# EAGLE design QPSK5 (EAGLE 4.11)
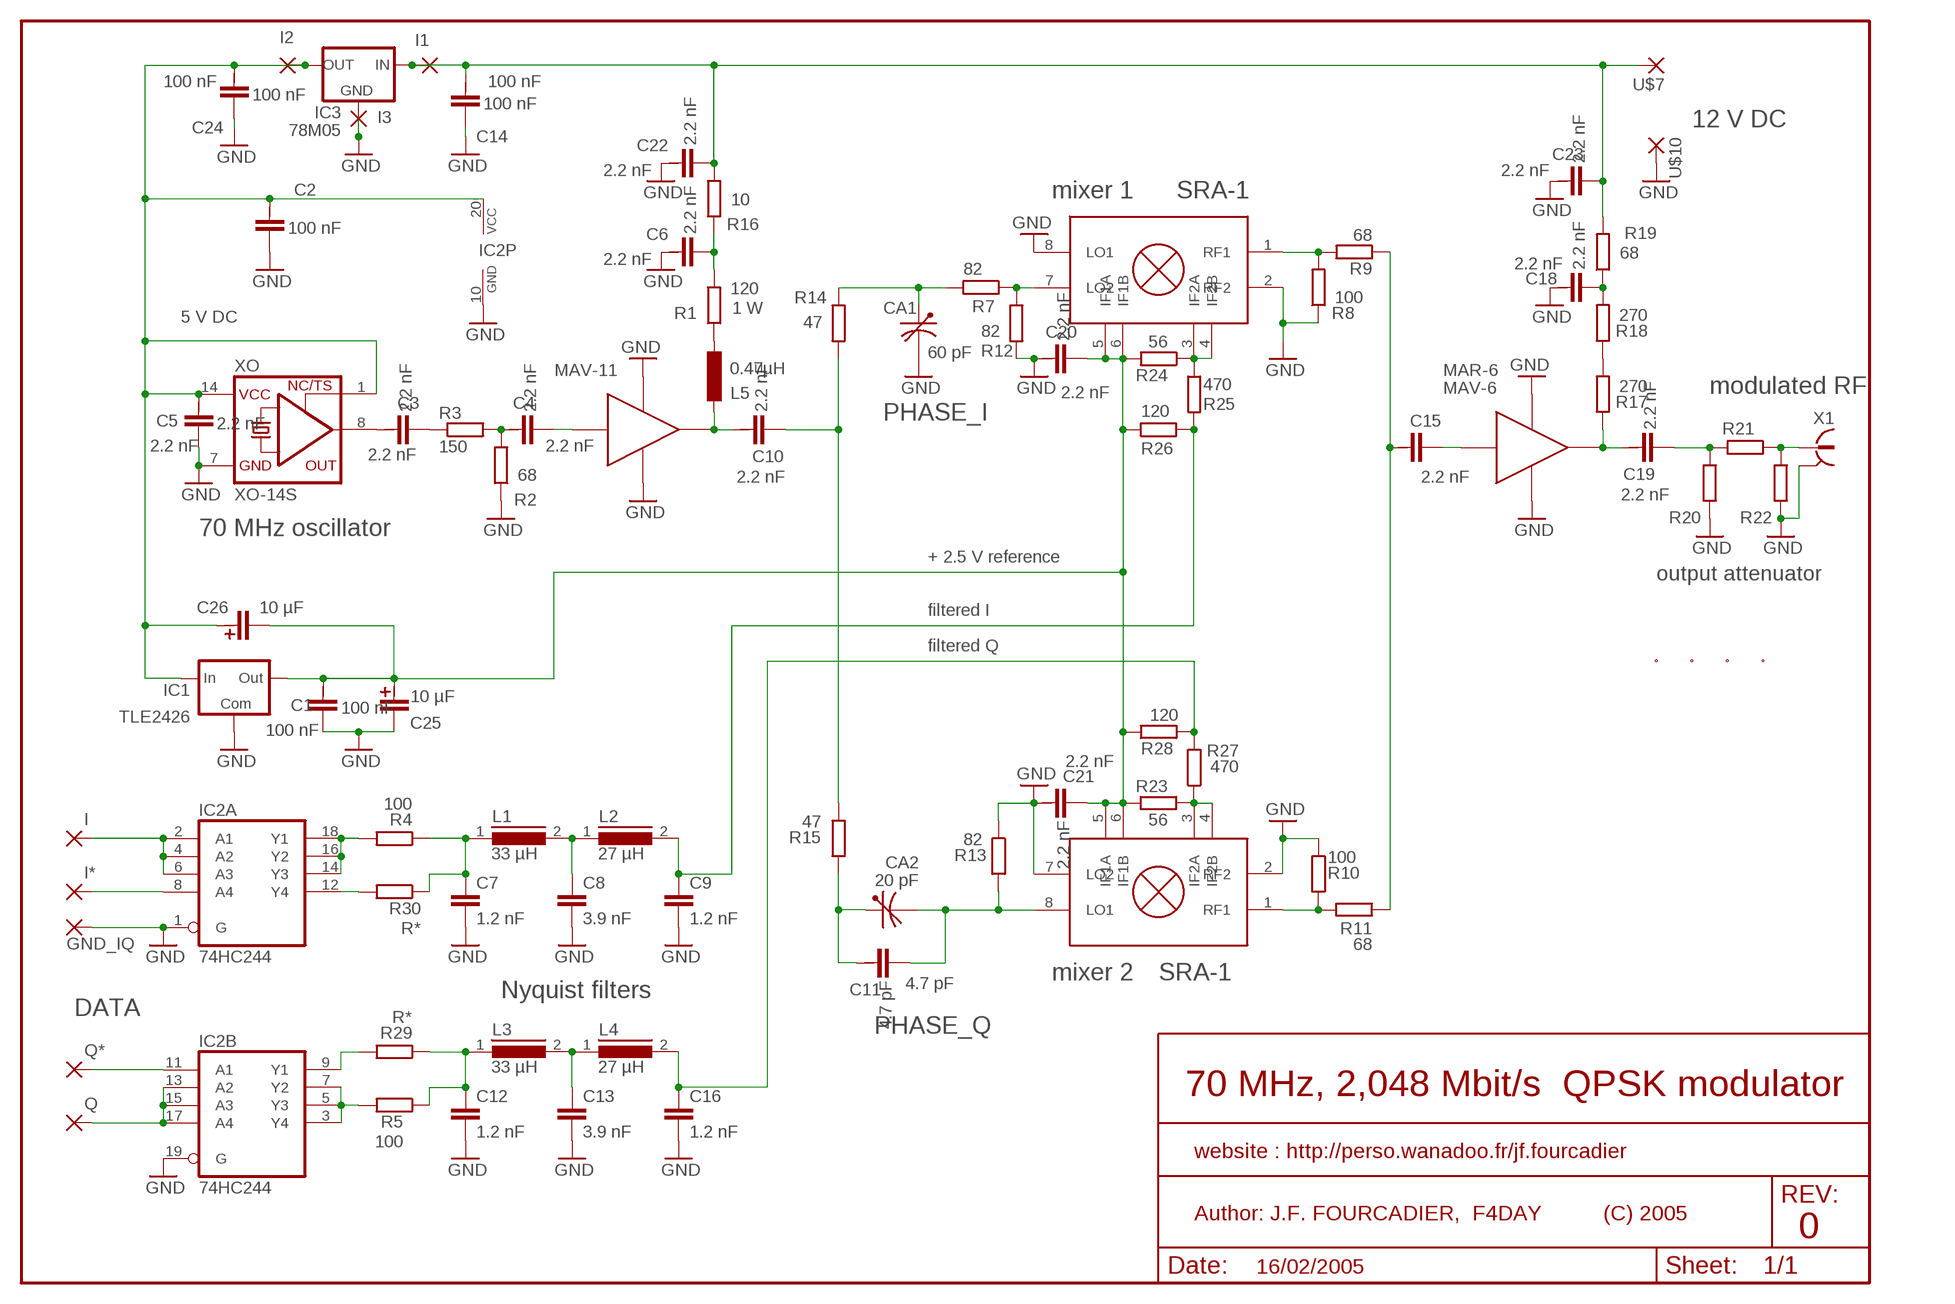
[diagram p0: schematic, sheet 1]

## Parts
C1  100 nF  C1206  [C1206]
C2  100 nF  C1206  [C1206]
C3  2.2 nF  C1206  [C1206]
C4  2.2 nF  C1206  [C1206]
C5  2.2 nF  C1206  [C1206]
C6  2.2 nF  C1206  [C1206]
C7  1.2 nF  C-EU050-035X075  [C050-035X075]
C8  3.9 nF  C-EU050-035X075  [C050-035X075]
C9  1.2 nF  C-EU050-035X075  [C050-035X075]
C10  2.2 nF  C1206  [C1206]
C11  4.7 pF  C1206  [C1206]
C12  1.2 nF  C-EU050-035X075  [C050-035X075]
C13  3.9 nF  C-EU050-035X075  [C050-035X075]
C14  100 nF  C1206  [C1206]
C15  C1206  [C1206]
C16  1.2 nF  C-EU050-035X075  [C050-035X075]
C18  2.2 nF  C1206  [C1206]
C19  2.2 nF  C1206  [C1206]
C20  2.2 nF  C1206  [C1206]
C21  2.2 nF  C1206  [C1206]
C22  2.2 nF  C1206  [C1206]
C23  2.2 nF  C1206  [C1206]
C24  100 nF  C1206  [C1206]
C25  10 µF  CT6032  [CT6032]
C26  10 µF  CT6032  [CT6032]
CA1  60 pF  MURATA  [MURATA_F]
CA2  20 pF  MURATA  [MURATA_F]
GND_IQ  2,54/0,4  [2,54/0,4]
I  2,54/0,4  [2,54/0,4]
I1  2,54/0,4  [2,54/0,4]
I2  2,54/0,4  [2,54/0,4]
I3  2,54/0,4  [2,54/0,4]
I*  2,54/0,4  [2,54/0,4]
IC1  TLE2426  TLE2425  [TLE2425]
IC2  74HC244  74HC244DW  [SO20W]
IC3  78M05  78XXL  [78XXL]
L1  33 µH  MMICC7  [MMICC7]
L2  27 µH  MMICC7  [MMICC7]
L3  33 µH  MMICC7  [MMICC7]
L4  27 µH  MMICC7  [MMICC7]
L5  0.47µH  L-EUL1210  [L1210]
MIX_1  SRA1  [SRA1]
MIX_2  SRA1  [SRA1]
MMIC_1  MAV-11  MAR  [MAR]
MMIC_2  MAR-8  MAR  [MAR]
Q  2,54/0,4  [2,54/0,4]
Q*  2,54/0,4  [2,54/0,4]
R1  120  R-EU_0309/12  [0309/12]
R2  68  R-EU_M1206  [M1206]
R3  150  R-EU_M1206  [M1206]
R4  100  R-EU_M1206  [M1206]
R5  100  R-EU_M1206  [M1206]
R7  82  R-EU_M1206  [M1206]
R8  100  R-EU_M1206  [M1206]
R9  68  R-EU_M1206  [M1206]
R10  100  R-EU_M1206  [M1206]
R11  68  R-EU_M1206  [M1206]
R12  82  R-EU_M1206  [M1206]
R13  82  R-EU_M1206  [M1206]
R14  47  R-EU_M1206  [M1206]
R15  47  R-EU_M1206  [M1206]
R16  10  R-EU_M1206  [M1206]
R17  270  R-EU_M1206  [M1206]
R18  270  R-EU_M1206  [M1206]
R19  68  R-EU_M1206  [M1206]
R20  R-EU_M1206  [M1206]
R21  R-EU_M1206  [M1206]
R22  R-EU_M1206  [M1206]
R23  56  R-EU_M1206  [M1206]
R24  56  R-EU_M1206  [M1206]
R25  470  R-EU_M1206  [M1206]
R26  120  R-EU_M1206  [M1206]
R27  470  R-EU_M1206  [M1206]
R28  120  R-EU_M1206  [M1206]
R29  R*  R-EU_M1206  [M1206]
R30  R*  R-EU_M1206  [M1206]
U$1  TROU_FIX  [TROU_FIX]
U$2  TROU_FIX  [TROU_FIX]
U$3  TROU_FIX  [TROU_FIX]
U$4  TROU_FIX  [TROU_FIX]
U$7  2,54/0,4  [2,54/0,4]
U$10  2,54/0,4  [2,54/0,4]
X1  ST-SMB-V  [ST-SMB-V]
XO  XO-14S  [DIL14S]

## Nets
GND: C1.2 C2.2 C5.2 C6.1 C7.2 C8.2 C9.2 C12.2 C13.2 C14.2 C16.2 C18.1 C20.1 C21.1 C22.1 C23.1 C24.2 C25.- CA1.2 GND_IQ.1(P) I3.1(P) IC1.COM IC2.1(A:G) IC2.10(P:GND) IC2.19(B:G) IC3.GND MIX_1.2(RF2) MIX_1.8(LO1) MIX_2.2(RF2) MIX_2.7(LO2) MMIC_1.GND@1(GND) MMIC_1.GND@2(GND) MMIC_2.GND@1(GND) MMIC_2.GND@2(GND) R2.1 R8.1 R10.1 R12.2 R13.1 R20.1 R22.1 U$10.1(P) X1.2(GND) XO.7(GND)
N$1: C3.1 XO.8(OUT)
N$2: C3.2 R3.1
N$3: C4.1 R2.2 R3.2
N$4: C4.2 MMIC_1.IN
N$5: L5.1 R1.1
N$6: MIX_1.1(RF1) R8.2 R9.2
N$7: MIX_2.1(RF1) R10.2 R11.2
N$8: C15.2 MMIC_2.IN
N$9: C15.1 R9.1 R11.1
N$10: C1.1 C20.2 C21.2 C25.+ C26.- IC1.OUT MIX_1.5(IF1A) MIX_1.6(IF1B) MIX_2.5(IF1A) MIX_2.6(IF1B) R23.2 R24.2 R26.1 R28.1
N$11: C16.1 L4.2 R27.2 R28.2
N$12: C10.2 R14.2 R15.2
N$13: MIX_1.3(IF2A) MIX_1.4(IF2B) R24.1 R25.1
N$14: CA1.1 R7.2 R14.1
N$15: C11.2 CA2.2 MIX_2.8(LO1) R13.2
N$16: C11.1 CA2.1 R15.1
N$18: C10.1 L5.2 MMIC_1.OUT
N$20: C9.1 L2.2 R25.2 R26.2
N$21: C6.2 R1.2 R16.1
N$22: R17.2 R18.1
N$23: C19.1 MMIC_2.OUT R17.1
N$24: C18.2 R18.2 R19.1
N$25: C19.2 R20.2 R21.2
N$26: R21.1 R22.2 X1.1
N$27: C14.1 C22.2 C23.2 I1.1(P) IC3.IN R16.2 R19.2 U$7.1(P)
N$28: C8.1 L1.2 L2.1
N$29: C13.1 L3.2 L4.1
N$31: IC2.3(B:Y4) IC2.5(B:Y3) IC2.7(B:Y2) R5.2
N$32: IC2.14(A:Y3) IC2.16(A:Y2) IC2.18(A:Y1) R4.2
N$33: C12.1 L3.1 R5.1 R29.1
N$34: IC2.9(B:Y1) R29.2
N$35: IC2.12(A:Y4) R30.2
N$36: IC2.13(B:A2) IC2.15(B:A3) IC2.17(B:A4) Q.1(P)
N$37: I.1(P) IC2.2(A:A1) IC2.4(A:A2) IC2.6(A:A3)
N$38: C7.1 L1.1 R4.1 R30.1
N$39: I*.1(P) IC2.8(A:A4)
N$40: IC2.11(B:A1) Q*.1(P)
N$52: MIX_1.7(LO2) R7.1 R12.1
N$59: MIX_2.3(IF2A) MIX_2.4(IF2B) R23.1 R27.1
VCC: C2.1 C5.1 C24.1 C26.+ I2.1(P) IC1.IN IC2.20(P:VCC) IC3.OUT XO.1(TS) XO.14(VCC)

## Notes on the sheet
- 100 nF | 100 nF
- 12 V DC
- 2.2 nF | 2.2 nF
- mixer 1 | SRA-1
- 2.2 nF | 2.2 nF
- 1 W
- 5 V DC
- MAV-11 | MAR-6
- 2.2 nF | MAV-6 | modulated RF
- PHASE_I
- 2.2 nF | 2.2 nF
- 2.2 nF
- 2.2 nF | 2.2 nF
- 2.2 nF
- 70 MHz oscillator
- + 2.5 V reference
- output attenuator
- filtered I
- filtered Q
- 100 nF
- 2.2 nF
- mixer 2 | SRA-1
- 4.7 pF
- Nyquist filters
- DATA
- PHASE_Q
- 70 MHz, 2,048 Mbit/s  QPSK modulator
- 0
- 16/02/2005

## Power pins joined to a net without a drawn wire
GND: X1.3(GND) X1.4(GND) X1.5(GND)

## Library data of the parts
C1-C6 C10 C11 C14 C15 C18-C24 = capacitor-smd:C
C7-C9 C12 C13 C16 = rcl:C-EU: CAPACITOR, European symbol
C25 C26 = capacitor-smd:CT
CA1 CA2 = cap_aj:MURATA
GND_IQ I I1-I3 I* Q Q* U$7 U$10 = wirepad:2,54/0,4
IC1 = v-reg:TLE2425
IC2 = 74xx-eu:74*244: Octal BUFFER and LINE DRIVER, 3-state
IC3 = v-reg:78XXL: VOLTAGE REGULATOR
L1-L4 = inductors:MMICC7: INDUCTOR
L5 = rcl:L-EU: INDUCTOR, European symbol
MIX_1 MIX_2 = mixer:SRA1
MMIC_1 MMIC_2 = mmic:MAR
R1-R5 R7-R30 = rcl:R-EU_: RESISTOR, European symbol
U$1-U$4 = holes:TROU_FIX
X1 = con-coax:ST-SMB-V: MALE SMB CONNECTOR Radiall distributor RS 193-8855G7
XO = crystal:XO-: CRYSTAL

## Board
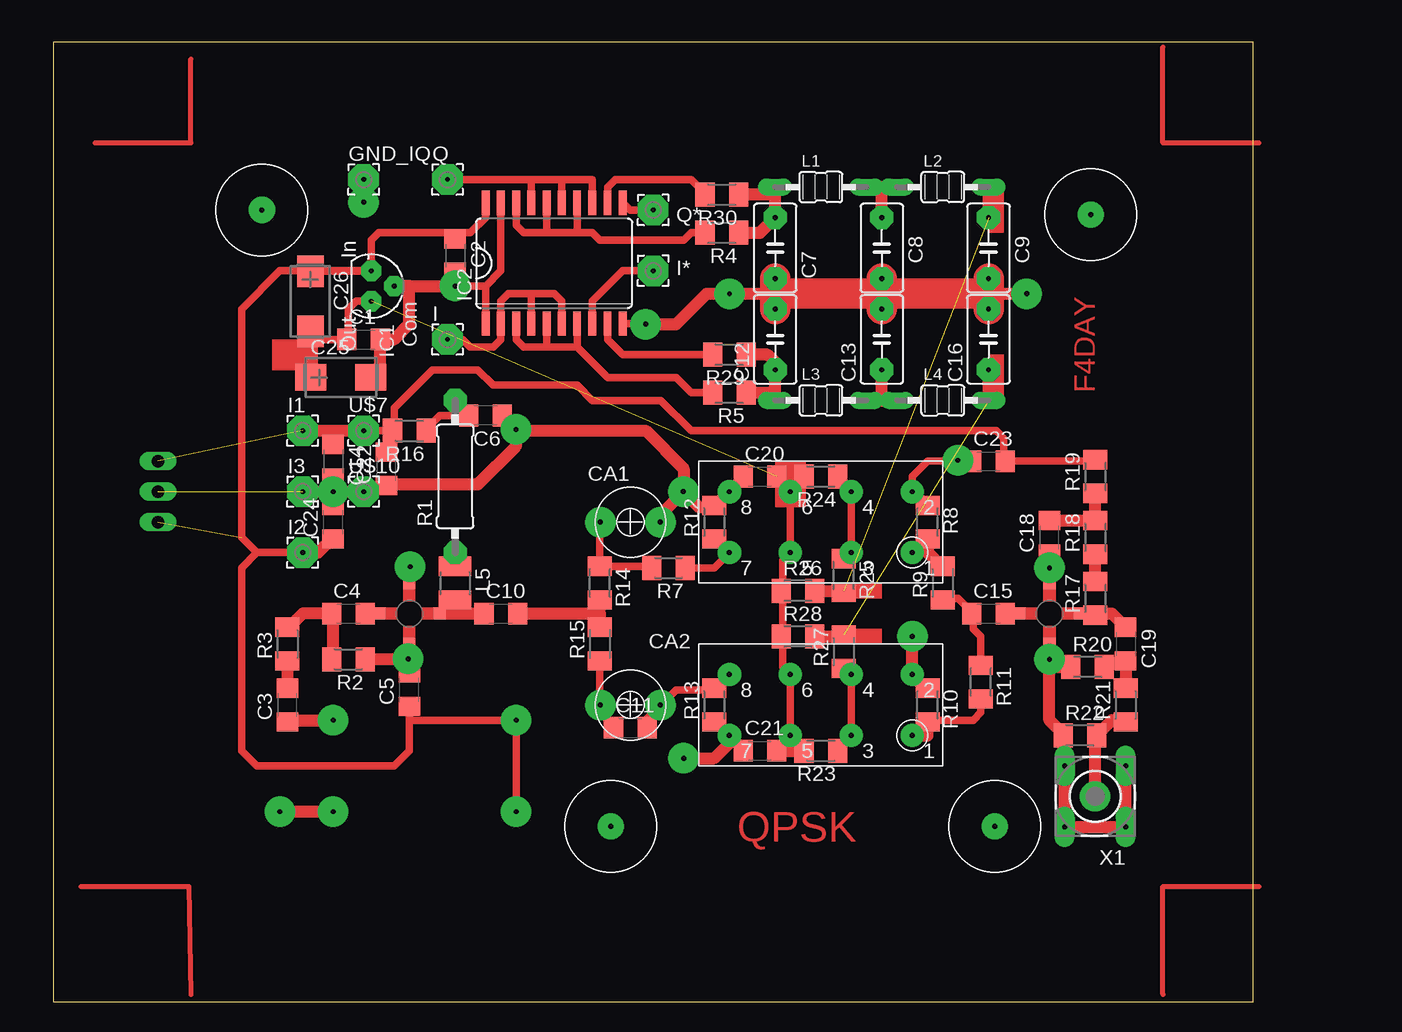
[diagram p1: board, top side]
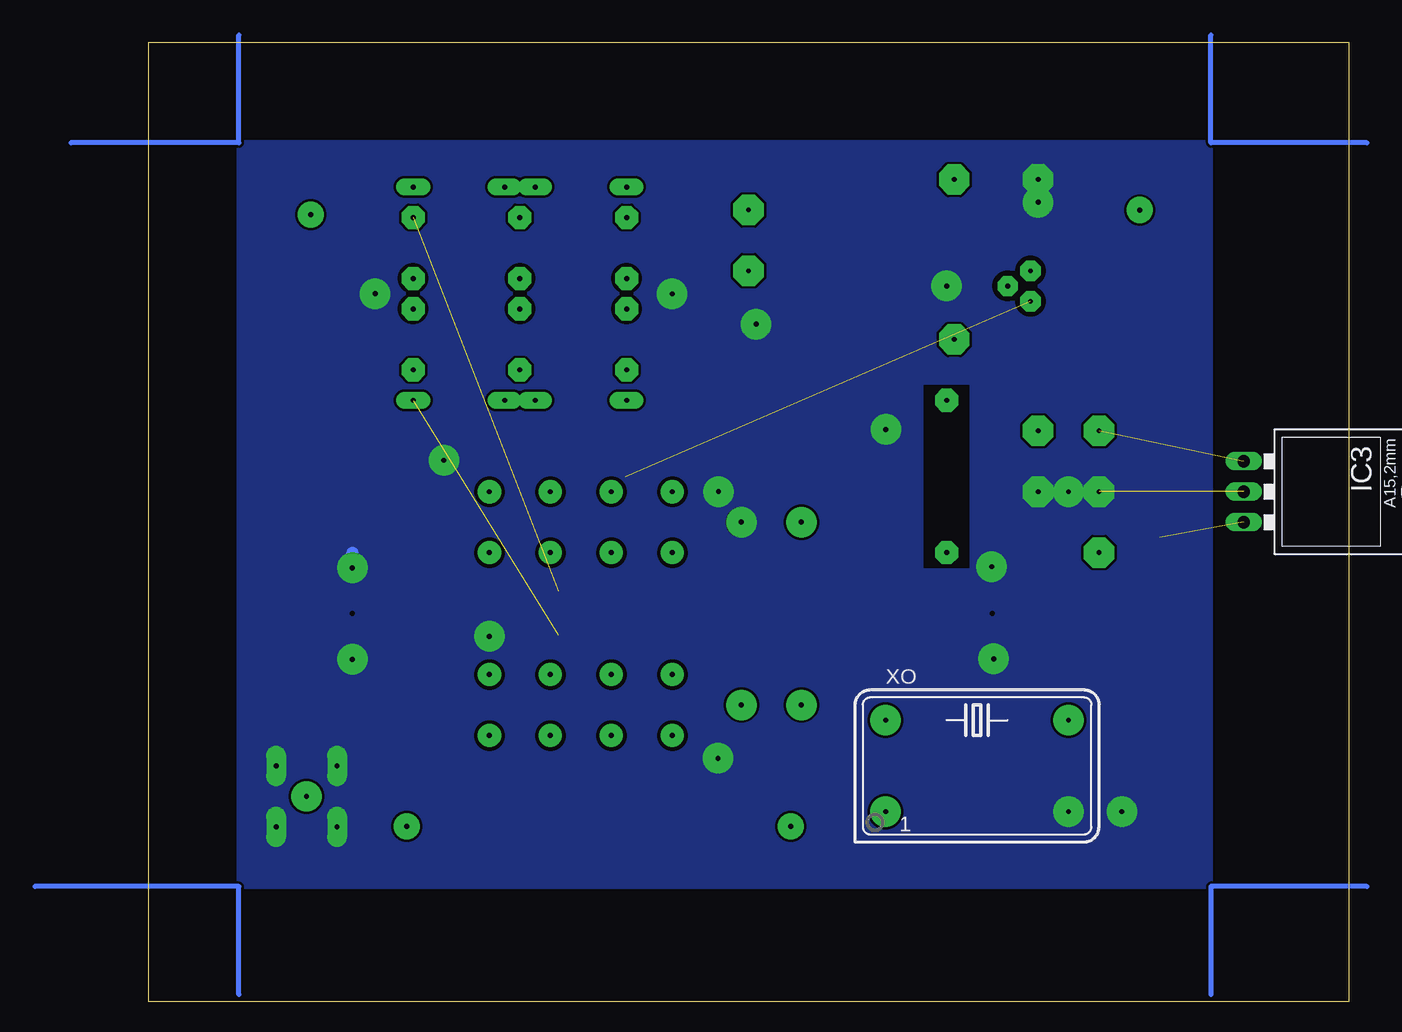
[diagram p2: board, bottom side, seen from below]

Size 100 x 80 mm. Coordinates in mm from the lower left corner, seen from the top.
Outline: 0,0 100,0 100,80 0,80 0,0
Copper layers (1*16): Top 0.035mm / dielectric 1.5mm / GND 0.035mm
Design rules "default": minimum track width 10mil, minimum drill 16mil, track to track 8mil, track to pad 8mil, pad to pad 8mil, via to via 8mil, smd to smd 8mil, copper to edge 40mil, drill to drill 8mil, minimum pad ring 10mil, minimum via ring 8mil, stop-mask expansion 4mil, vias tented up to drill 0mil, thermal gap 10mil
bRestrict: area 31.6,36.2 to 35.4,51.4

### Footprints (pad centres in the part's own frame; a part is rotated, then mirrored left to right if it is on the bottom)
C1206 = smd 1.6 x 1.8: 1 -1.4,0; 2 1.4,0
C050-035X075 = drill 0.406 pad 1.93 octagon: 1 -2.54,0; 2 2.54,0
CT6032 = smd 2.6 x 2.2: + -2.5,0; - 2.5,0
MURATA_F = drill 0.406 pad 2.54 round: 1 -2.5,0; 2 2.5,0
2,54/0,4 = drill 0.406 pad 2.54 octagon: 1 0,0
TLE2425 = drill 0.406 pad 1.676 octagon: COM 0,1.905; IN -1.27,0; OUT 1.27,0
SO20W = smd 0.66 x 2.032: 1 -5.715,-5.029; 2 -4.445,-5.029; 3 -3.175,-5.029; 4 -1.905,-5.029; 5 -0.635,-5.029; 6 0.635,-5.029; 7 1.905,-5.029; 8 3.175,-5.029; 9 4.445,-5.029; 10 5.715,-5.029; 11 5.715,5.029; 12 4.445,5.029; 13 3.175,5.029; 14 1.905,5.029; 15 0.635,5.029; 16 -0.635,5.029; 17 -1.905,5.029; 18 -3.175,5.029; 19 -4.445,5.029; 20 -5.715,5.029
78XXL = drill 1.016 long: GND 0,-3.81; IN -2.54,-3.81; OUT 2.54,-3.81 | hole 3.302: 0,11.176
MMICC7 = drill 0.406 pad 1.422 long: 1 -3.81,0; 2 3.81,0
L1210 = smd 1.6 x 2.7: 1 -1.4,0; 2 1.4,0
SRA1 = drill 0.406 pad 1.93 round: 1 -7.62,2.54; 2 -7.62,-2.54; 3 -2.54,2.54; 4 -2.54,-2.54; 5 2.54,2.54; 6 2.54,-2.54; 7 7.62,2.54; 8 7.62,-2.54
MAR = smd 1.016 x 1.016: GND@1 0,2.54; GND@2 0,-2.54; IN -2.54,0; OUT 2.54,0
0309/12 = drill 0.406 pad 1.93 octagon: 1 -6.35,0; 2 6.35,0
M1206 = smd 1.6 x 2: 1 -1.4,0; 2 1.4,0
TROU_FIX = drill 0.406 pad 2.184 round: P 0,0
ST-SMB-V = drill 0.406 pad 2.54 round: 1 0,0 | drill 0.406 pad 1.676 long: 2 -2.54,2.54; 3 2.54,2.54; 4 2.54,-2.54; 5 -2.54,-2.54
DIL14S = drill 0.406 pad 2.54 round: 1 -7.62,-3.81; 7 7.62,-3.81; 8 7.62,3.81; 14 -7.62,3.81

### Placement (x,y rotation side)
C1  25.87,55.24 0 top
C2  33.49,62.23 270 top
C3  19.52,24.76 90 top
C4  24.6,32.38 0 top
C5  29.68,26.03 90 top
C6  36.03,48.89 180 top
C7  60.16,62.86 270 top
C8  69.05,62.86 270 top
C9  77.94,62.86 270 top
C10  37.3,32.38 0 top
C11  48.09,22.86 0 top
C12  60.16,55.24 90 top
C13  69.05,55.24 90 top
C14  23.33,45.08 270 top
C15  77.94,32.38 0 top
C16  77.94,55.24 90 top
C18  83.02,38.73 90 top
C19  89.37,29.84 270 top
C20  58.89,43.81 0 top
C21  58.89,20.95 0 top
C22  27.77,44.45 90 top
C23  77.94,45.08 0 top
C24  23.33,40 90 top
C25  23.96,52.07 0 top
C26  21.42,58.41 270 top
CA1  48.09,40 0 top
CA2  48.09,24.76 0 top
GND  [DET_100]  25.87,68.57 0 top
GND_IQ  25.87,68.57 0 top
I  32.85,55.24 0 top
I1  20.79,47.62 0 top
I2  20.79,37.46 0 top
I3  20.79,42.54 0 top
I*  50,60.96 0 top
IC1  26.5,59.69 270 top
IC2  41.74,61.59 0 top
IC3  4.92,42.54 270 bottom
L1  63.97,67.94 0 top
L2  74.13,67.94 0 top
L3  63.97,50.16 0 top
L4  74.13,50.16 0 top
L5  33.49,34.92 270 top
MIX_1  63.97,40 180 top
MIX_2  63.97,24.76 180 top
MMIC_1  29.68,32.38 0 top
MMIC_2  83.02,32.38 0 top
N$15  [DET_100]  50.63,24.76 0 top
Q  32.85,68.57 0 top
Q*  50,66.03 0 top
R1  33.49,43.81 90 top
R2  24.6,28.57 180 top
R3  19.52,29.84 90 top
R4  55.71,64.13 180 top
R5  56.35,50.8 180 top
R7  51.27,36.19 180 top
R8  72.86,40 270 top
R9  74.13,34.92 90 top
R10  72.86,24.76 270 top
R11  77.3,26.66 270 top
R12  55.08,40 90 top
R13  55.08,24.76 90 top
R14  45.55,34.92 270 top
R15  45.55,29.84 90 top
R16  29.68,47.62 180 top
R17  86.83,33.65 90 top
R18  86.83,38.73 90 top
R19  86.83,43.81 90 top
R20  86.19,27.93 0 top
R21  89.37,24.76 90 top
R22  85.56,22.22 0 top
R23  63.97,20.95 180 top
R24  63.97,43.81 180 top
R25  65.88,35.55 270 top
R26  62.06,34.29 0 top
R27  65.88,29.2 90 top
R28  62.06,30.47 0 top
R29  56.35,53.97 180 top
R30  55.71,67.3 180 top
U$1  17.39,66.03 0 top
U$2  86.47,65.63 0 top
U$3  78.47,14.63 0 top
U$4  46.47,14.63 0 top
U$5  [DET_100]  60.16,60.32 0 top
U$6  [DET_100]  20.79,42.54 0 top
U$7  25.87,47.62 0 top
U$8  [DET_100]  25.87,42.54 0 top
U$9  [DET_100]  69.05,60.32 0 top
U$10  25.87,42.54 0 top
U$11  [DET_100]  23.33,23.49 0 top
U$12  [DET_100]  38.57,23.49 0 top
U$13  [DET_100]  38.57,15.87 0 top
U$14  [DET_100]  23.33,15.87 0 top
U$18  [DET_100]  77.94,60.32 0 top
U$19  [DET_100]  60.16,57.78 0 top
U$20  [DET_100]  69.05,57.78 0 top
U$21  [DET_100]  77.94,57.78 0 top
U$22  [DET_100]  45.55,40 0 top
U$23  [DET_100]  50.63,40 0 top
U$24  [DET_100]  45.55,24.76 0 top
U$25  [DET_100]  32.85,68.57 0 top
U$26  [DET_100]  32.85,55.24 0 top
U$27  [DET_100]  50,60.96 0 top
U$28  [DET_100]  50,66.03 0 top
U$36  [DET_100]  56.35,42.54 0 top
U$37  [DET_100]  61.43,42.54 0 top
U$38  [DET_100]  66.51,42.54 0 top
U$39  [DET_100]  71.59,42.54 0 top
U$40  [DET_100]  71.59,37.46 0 top
U$41  [DET_100]  66.51,37.46 0 top
U$42  [DET_100]  61.43,37.46 0 top
U$43  [DET_100]  56.35,37.46 0 top
U$44  [DET_100]  56.35,27.3 0 top
U$45  [DET_100]  61.43,27.3 0 top
U$46  [DET_100]  66.51,27.3 0 top
U$47  [DET_100]  71.59,27.3 0 top
U$48  [DET_100]  71.59,22.22 0 top
U$49  [DET_100]  66.51,22.22 0 top
U$50  [DET_100]  61.43,22.22 0 top
U$51  [DET_100]  56.35,22.22 0 top
U$52  [DET_100]  20.79,42.54 0 top
U$53  [DET_100]  25.87,47.62 0 top
X1  86.83,17.14 180 top
XO  30.95,19.68 0 bottom

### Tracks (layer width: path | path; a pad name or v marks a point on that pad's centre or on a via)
GND  (via drill 0.41 pad 2.54)  (1 unrouted)
  Top 0.61: C22.1 26.38,43.05 U$10.1 | 36.03,56.51 IC2.1 36.03,59.69 | IC2.19 37.3,60.96 36.03,59.69 | 33.99,61.09 33.99,60.19 v33.49,59.69 | v33.49,59.69 36.03,59.69 | C6.1 37.3,48.89 38.45,47.73 v38.56,47.73 38.56,47.63 38.57,47.62 | 72.86,26.03 R10.1 72.73,26.16 | v49.37,56.51 48.68,56.56 IC2.10 | C23.1 72.86,45.08 71.59,43.81 MIX_1.2 | v33.49,59.69 C2.2
  Top 1.016: v18.88,15.87 XO.7 | 23.33,43.81 C14.2 v23.33,42.54 | v23.33,42.54 C24.2 | v23.33,42.54 U$10.1 | v23.33,42.54 I3.1 U$10.1 | 29.68,28.57 C5.2 | 29.68,28.57 MMIC_1.GND@2 | 29.68,28.57 29.68,27.3 | 29.68,28.57 29.68,28.61 | 29.68,28.57 29.68,28.6 v29.57,28.6 25.9,28.6 25.87,28.57 R2.1 | 29.68,36.29 29.68,36.19 | 29.68,36.29 v29.74,36.29 | MMIC_1.GND@1 29.68,36.29 | 29.68,59.69 IC1.COM | 29.68,59.69 v33.49,59.69 | 29.68,59.69 29.68,56.51 28.41,55.24 C1.2 | C25.- 27.14,52.07 27.27,52.2 C1.2 | 52.54,42.54 52.54,44.45 49.37,47.62 38.57,47.62 38.57,46.35 35.39,43.18 27.77,43.18 U$10.1 | C20.1 57.62,43.81 MIX_1.8 55.21,41.4 R12.2 55.08,41.27 53.78,41.27 v52.5,42.55 | R20.1 83.66,27.93 v83.02,28.57 | v83.02,28.57 MMIC_2.GND@2 | v83.02,28.57 83.02,30.47 | v83.02,28.57 83.02,23.49 84.29,22.22 | 84.29,22.22 84.29,19.84 84.37,19.76 X1.4 | 84.29,22.22 R22.1 84.16,19.81 X1.4 | X1.4 84.29,22.22 | X1.4 84.29,14.76 84.37,14.68 X1.3 X1.2 X1.5 | v71.59,30.47 MIX_2.2 72.73,26.16 | 77.94,59.05 v81.11,59.05 | v56.36,59.04 v56.35,59.05 | v56.35,59.05 60.16,59.05 | v56.35,59.05 55.71,59.05 | v56.35,59.05 54.45,59.05 51.91,56.51 v49.37,56.51 | v75.39,45.16 76.59,45.16 76.67,45.08 C23.1 | R8.1 72.86,41.27 MIX_1.2 | C18.1 83.02,37.46 | v83.02,36.19 C18.1 | v83.02,36.19 C18.1 | v83.02,36.19 MMIC_2.GND@1 v83.02,36.19 | C1.2 27.14,55.24 | 52.54,42.54 v52.51,42.54 v52.5,42.55 | C21.1 57.62,20.95 56.67,21.9 | R13.1 55.21,23.36 MIX_2.7 56.67,21.9 | 52.54,42.54 52.53,42.55 v52.5,42.55 | CA1.2 50.59,40.6 52.54,42.54 | v52.54,20.31 55.08,20.31 56.67,21.9
  Top 2.54: 77.94,59.05 C9.2 | 77.94,59.05 C16.2 | 69.05,59.05 C13.2 | 69.05,59.05 C8.2 | 69.05,59.05 77.94,59.05 | 60.16,59.05 C12.2 | 60.16,59.05 C7.2 | 60.16,59.05 69.05,59.05
  GND 1.016: 29.68,28.57 29.6,28.65 | v83.02,28.57 82.92,28.67 | v83.02,36.19 83.02,37.46
  other vias: 25.87,66.67
  pour GND (no thermals): 11.47,71.63 92.47,71.63 92.47,9.63 11.47,9.63
N$1
  Top 1.016: C3.1 19.52,23.49 XO.8
N$2
  Top 1.016: 19.52,28.57 R3.1 C3.2
N$3
  Top 1.016: R2.2 23.33,28.57 23.33,32.38 C4.1 20.79,32.38 19.52,31.11 R3.2
N$4
  Top 1.016: MMIC_1.IN C4.2 MMIC_1.IN
N$5
  Top 1.016: 33.49,36.19 L5.1 R1.1
N$6
  Top 1.016: 74.13,36.19 R9.2 74,36.32 72.86,37.46 R8.2 | R8.2 72.73,38.6 MIX_1.1 | R8.2 72.86,38.73
N$7
  Top 0.61: R10.2 72.86,23.49 76.67,23.49 77.3,24.12 R11.2
  Top 1.016: MIX_2.1 72.86,22.22 R10.2
N$8
  Top 0.813: C15.2 79.56,32.7
  Top 1.016: MMIC_2.IN C15.2 MMIC_2.IN
N$9
  Top 0.61: C15.1 76.54,32.51 75.4,33.65 74.13,33.65 R9.1 | 76.67,32.38 76.67,31.11 77.3,30.47 R11.1
  Top 1.016: 76.67,32.38 C15.1
N$10  (1 unrouted)
  Top 0.61: 62.7,20.95 R23.2 61.43,20.95 MIX_2.5 MIX_2.6 60.8,27.93 60.8,30.47 60.8,34.16 | 60.8,34.29 60.8,36.83 MIX_1.5 MIX_1.6 | IC1.OUT 25.23,58.41 24.6,57.78 24.6,55.24 C1.1 22.06,55.24 21.42,55.88 C26.- 21.42,52.07 C25.+
  Top 1.016: 60.8,30.47 R28.1 | 60.8,34.16 R26.1 60.8,34.29 | MIX_1.6 62.7,43.81 R24.2 C20.2 | 60.16,20.95 C21.2 62.7,20.95
N$11  (1 unrouted)
  Top 1.016: R27.2 65.88,30.47 R28.2 | L4.2 C16.1
N$12
  Top 0.813: C10.2 38.92,32.7
  Top 1.016: C10.2 45.55,32.38 | 45.55,32.38 R15.2 | 45.55,33.65 R14.2 45.55,32.38
N$13
  Top 0.61: MIX_1.3 MIX_1.4
  Top 1.016: R25.1 65.88,36.83 MIX_1.3 | 65.24,43.81 R24.1 65.37,43.68 MIX_1.4
N$14
  Top 0.61: CA1.1 45.55,40 R14.1 50,36.32 50,36.19 R7.2
N$15
  Top 0.61: C11.2 49.49,23.62 50.63,24.76 | 50.63,24.76 CA2.2 | 50.63,24.76 51.91,26.03 55.08,26.03 R13.2 55.21,26.16 MIX_2.8
N$16
  Top 0.61: R15.1 45.55,24.76 CA2.1 45.59,24.08 46.82,22.86 C11.1
N$18
  Top 1.016: 36.03,32.38 C10.1 33.49,32.38 | MMIC_1.OUT 33.49,32.38 | 33.49,32.38 L5.2
N$20  (1 unrouted)
  Top 1.016: R25.2 65.88,34.29 R26.2 | C9.1 L2.2
N$21
  Top 0.61: 34.76,48.89 C6.2 33.49,48.89 | 30.95,47.62 R16.1 31.08,47.75 32.22,48.89 33.49,48.89 | 33.49,48.89 R1.2
N$22
  Top 1.016: 86.83,37.46 R18.1 R17.2
N$23
  Top 1.016: C19.1 88.23,32.38 86.83,32.38 | 86.77,32.31 86.7,32.38 | 86.77,32.31 R17.1 86.83,32.38 | 86.83,32.38 86.77,32.31 | MMIC_2.OUT 86.83,32.38
N$24
  Top 1.016: R18.2 R19.1 | C18.2 R18.2 | R18.2 86.83,40
N$25
  Top 1.016: R21.2 C19.2 89.24,28.57 R20.2
N$26
  Top 1.016: 86.83,22.22 R22.2 88.23,23.49 89.37,23.49 R21.1 | 86.83,22.22 86.99,22.06 | X1.1 86.83,22.22
N$27  (1 unrouted)
  Top 0.61: C23.2 86.83,45.08 | 79.21,45.08 79.21,46.98 78.58,47.62 53.17,47.62 50.63,50.16 44.92,50.16 43.65,51.43 36.66,51.43 35.39,52.7 31.58,52.7 28.41,49.53 28.41,47.62 | 28.41,47.62 R16.2 U$7.1 | C22.2 27.77,46.98 28.41,47.62
  Top 1.016: 86.83,45.08 R19.2 | 79.21,45.08 C23.2 | 23.33,47.62 U$7.1 | 23.33,47.62 C14.1 | I1.1 23.33,47.62
N$28
  Top 1.016: 69.05,67.94 L1.2 | 69.05,67.94 L2.1 | C8.1 69.05,67.94
N$29
  Top 1.016: L3.2 69.05,50.16 | 69.05,50.16 L4.1 | 69.05,50.16 C13.1
N$30
  GND 0.406: -1.53,71.63 11.47,71.63 11.47,80.63
N$31
  Top 0.61: IC2.3 38.57,55.24 39.2,54.61 41.11,54.61 | 41.11,54.61 IC2.5 | 41.11,54.61 43.65,54.61 | 43.65,54.61 IC2.7 | 43.65,54.61 46.19,52.07 51.91,52.07 53.17,50.8 R5.2 55.08,50.8
N$32
  Top 0.61: 43.65,66.67 IC2.14 43.65,64.13 | 41.11,64.13 43.65,64.13 | 41.11,64.13 IC2.16 | 41.11,64.13 39.2,64.13 38.57,64.77 IC2.18 38.57,66.67 | 43.65,64.13 44.92,64.13 45.55,63.5 52.54,63.5 53.17,64.13 R4.2 54.45,64.13
N$33
  Top 0.61: 57.62,53.97 R29.1
  Top 1.016: 60.16,50.8 L3.1 | 60.16,50.8 C12.1 60.16,53.34 59.52,53.97 57.62,53.97 | R5.1 60.16,50.8
N$34
  Top 0.61: IC2.9 46.19,55.24 47.46,53.97 R29.2 55.08,53.97
N$35
  Top 0.61: IC2.12 46.19,67.94 46.82,68.57 53.17,68.57 54.45,67.3 R30.2
N$36
  Top 0.61: 42.38,68.57 IC2.15 | 44.92,68.57 42.38,68.57 | 44.92,68.57 IC2.13 | IC2.17 39.84,68.57 42.38,68.57 | Q.1 44.92,68.57
N$37
  Top 0.61: 39.84,56.51 IC2.4 39.84,59.05 | 42.38,56.51 IC2.6 42.38,58.41 41.74,59.05 39.84,59.05 | 39.84,59.05 37.94,59.05 37.3,58.41 IC2.2 37.3,55.24 36.66,54.61 34.76,54.61 34.12,55.24 I.1
N$38
  Top 0.61: R30.1 56.98,67.3 57.12,67.17
  Top 1.016: 60.16,67.3 C7.1 58.89,64.13 R4.1 | 60.16,67.3 L1.1 | 60.16,67.3 R30.1
N$39
  Top 0.61: 44.92,56.51 IC2.8 44.92,58.41 47.46,60.96 I*.1
N$40
  Top 0.61: IC2.11 47.51,66.62 48.09,66.03 Q*.1
N$41
  GND 0.406: 92.47,80.63 92.47,71.63 106.47,71.63
N$44
  Top 0.406: 11.47,78.63 11.47,71.63 3.47,71.63
N$45
  Top 0.406: 2.31,9.63 11.31,9.63 11.47,0.63
N$46
  Top 0.406: 100.47,71.63 92.47,71.63 92.47,79.63
N$47
  Top 0.406: 100.47,9.63 92.47,9.63 92.47,0.63
N$50
  GND 0.406: -1.53,9.63 11.47,9.63 11.47,0.63
N$51
  GND 0.406: 92.47,0.63 92.47,9.63 109.47,9.63
N$52
  Top 0.61: R12.1 55.08,38.73 MIX_1.7 55.08,36.19 R7.1
N$59
  Top 0.61: 65.37,21.08 MIX_2.3 MIX_2.4 | 66,27.8 R27.1
  Top 1.016: R23.1 65.37,21.08 | MIX_2.4 66,27.8
S$3
  Top 1.016: 56.35,42.67 56.48,42.67
VCC  (1 unrouted)
  Top 0.61: 36.03,66.67 IC2.20 36.03,65.4 34.76,64.13 33.49,64.13 | XO.1 XO.14 29.68,23.49 | 16.98,37.46 15.71,38.73 15.71,57.78 18.88,60.96 IC1.IN | 16.98,37.46 15.71,36.19 15.71,20.95 16.98,19.68 28.41,19.68 29.68,20.95 29.68,23.49 | 16.98,37.46 I2.1 | 33.49,64.13 27.14,64.13 26.5,63.5 IC1.IN | C26.+ 26.46,60.91 IC1.IN | 29.68,24.76 C5.1 29.68,23.49 | 33.49,64.13 C2.1
  Top 1.016: I2.1 22.06,37.46 23.33,38.73 C24.1
(copper drawn outside any net)
  shapes: Top area x6

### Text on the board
Top: F4DAY | QPSK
